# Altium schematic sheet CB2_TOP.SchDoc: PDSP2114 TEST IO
size A2; Engineer: SHOWELL; DocumentNumber: 1; Revision: 1.00; SheetNumber: 1; SheetTotal: 1; PageSetup: Record=PageOptions|CenterHorizontal=True|CenterVertical=True|PrintScale=1.47|XCorrection=1.00|YCorrection=1.00|PrintKind=0|BorderSize=5000000|LeftOffset=0|BottomOffset=0|Orientation=2|PaperLength=1000|PaperWidth=1000|Scale=100|PaperSource=7|PrintQuality=-4|MediaType=1|DitherType=10|PaperKind=A2|PrintScaleMode=1
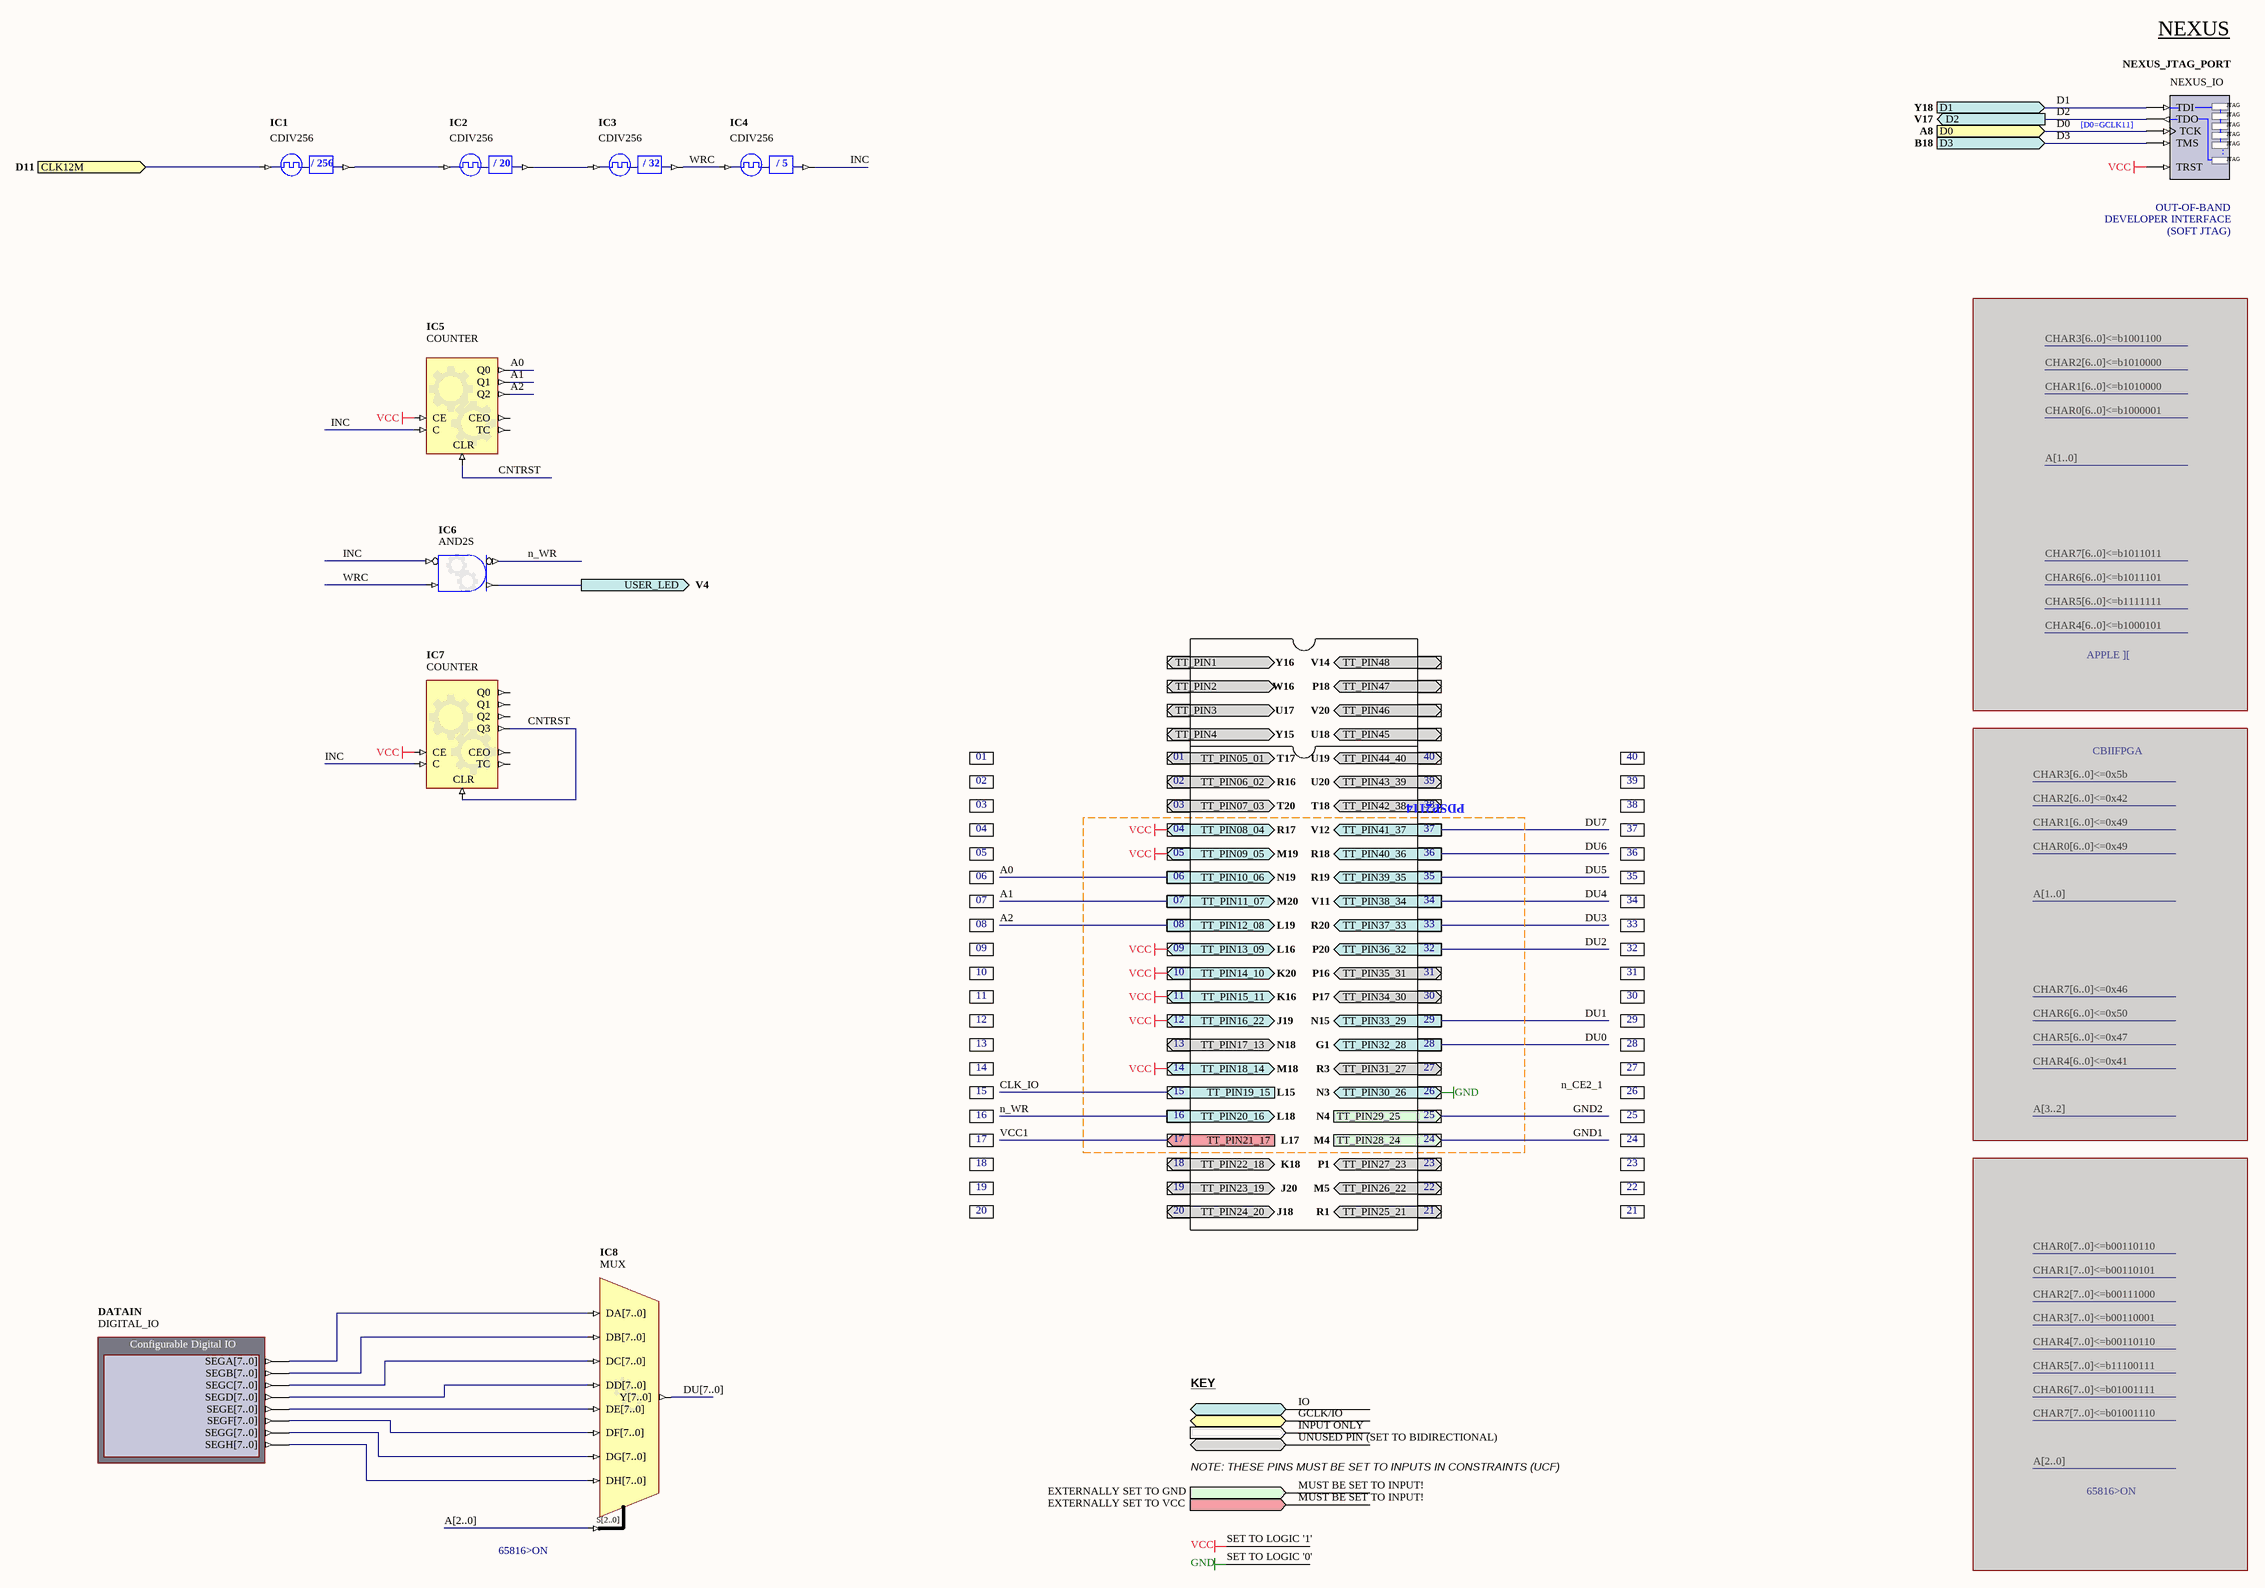
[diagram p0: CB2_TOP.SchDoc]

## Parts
DATAIN  DIGITAL_IO
IC1  CDIV256
IC2  CDIV256
IC3  CDIV256
IC4  CDIV256
IC5  COUNTER
IC6  AND2S
IC7  COUNTER
IC8  MUX
NEXUS_JTAG_PORT  NEXUS_IO

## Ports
CLK12M (in, see D11), D0 (in, see A8), D1 (in, see Y18), D2 (out, see V17), D3 (in, see B18), TT_PIN1 (bidir, see Y16), TT_PIN2 (bidir, see W16), TT_PIN3 (bidir, see U17), TT_PIN4 (bidir, see Y15), TT_PIN05_01 (bidir, see T17), TT_PIN06_02 (bidir, see R16), TT_PIN07_03 (bidir, see T20), TT_PIN08_04 (out, see R17), TT_PIN09_05 (out, see M19), TT_PIN10_06 (out, see N19), TT_PIN11_07 (out, see M20), TT_PIN12_08 (out, see L19), TT_PIN13_09 (out, see L16), TT_PIN14_10 (out, see K20), TT_PIN15_11 (out, see K16), TT_PIN16_22 (out, see J19), TT_PIN17_13 (bidir, see N18), TT_PIN18_14 (out, see M18), TT_PIN19_15 (in, see L15), TT_PIN20_16 (out, see L18), TT_PIN21_17 (in, see L17), TT_PIN22_18 (bidir, see K18), TT_PIN23_19 (bidir, see J20), TT_PIN24_20 (bidir, see J18), TT_PIN25_21 (bidir, see R1), TT_PIN26_22 (bidir, see M5), TT_PIN27_23 (bidir, see P1), TT_PIN28_24 (in, see M4), TT_PIN29_25 (in, see N4), TT_PIN30_26 (out, see N3), TT_PIN31_27 (bidir, see R3), TT_PIN32_28 (out, see G1), TT_PIN33_29 (out, see N15), TT_PIN34_30 (bidir, see P17), TT_PIN35_31 (bidir, see P16), TT_PIN36_32 (out, see P20), TT_PIN37_33 (out, see R20), TT_PIN38_34 (out, see V11), TT_PIN39_35 (out, see R19), TT_PIN40_36 (out, see R18), TT_PIN41_37 (out, see V12), TT_PIN42_38 (bidir, see T18), TT_PIN43_39 (bidir, see U20), TT_PIN44_40 (bidir, see U19), TT_PIN45 (bidir, see U18), TT_PIN46 (bidir, see V20), TT_PIN47 (bidir, see P18), TT_PIN48 (bidir, see V14), USER_LED (out, see V4)

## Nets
VCC: IC5.CE IC7.CE NEXUS_JTAG_PORT.TRST ; port TT_PIN09_05, port TT_PIN13_09, port TT_PIN16_22, port TT_PIN15_11, port TT_PIN14_10, port TT_PIN18_14, port TT_PIN08_04
A0: IC5.Q0 ; port TT_PIN10_06
A1: IC5.Q1 ; port TT_PIN11_07
A2: IC5.Q2 ; port TT_PIN12_08
CLK12M: IC1.CLKIN ; port CLK12M
CNTRST: IC5.CLR IC7.CLR IC7.Q3
D0: NEXUS_JTAG_PORT.TCK ; port D0
D1: NEXUS_JTAG_PORT.TDI ; port D1
D2: NEXUS_JTAG_PORT.TDO ; port D2
D3: NEXUS_JTAG_PORT.TMS ; port D3
INC: IC4.CLKDV IC5.C IC6.I0 IC7.C
n_WR: IC6.NO ; port TT_PIN20_16
USER_LED: IC6.O ; port USER_LED
WRC: IC3.CLKDV IC4.CLKIN IC6.I1
NetIC1_CLKDV: IC1.CLKDV IC2.CLKIN
NetIC2_CLKDV: IC2.CLKDV IC3.CLKIN

Not connected (* = marked no-connect by the designer): DATAIN SEGA[7..0] SEGB[7..0] SEGC[7..0] SEGD[7..0] SEGE[7..0] SEGF[7..0] SEGG[7..0] SEGH[7..0]; IC5 CEO TC; IC7 CEO Q0 Q1 Q2 TC; IC8 DA[7..0] DB[7..0] DC[7..0] DD[7..0] DE[7..0] DF[7..0] DG[7..0] DH[7..0] S[2..0] Y[7..0]

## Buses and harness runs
bus A[2..0]
bus DU[7..0]

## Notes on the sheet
- NEXUS
- (near NEXUS_JTAG_PORT) [D0=GCLK11]
- DEVELOPER INTERFACE
- (near NEXUS_JTAG_PORT) OUT-OF-BAND
- (SOFT JTAG)
- APPLE ][
- 01
- 02
- 40
- 39
- CBIIFPGA
- 03
- 04
- 38
- 37
- PDSP2114
- 05
- 06
- 07
- 36
- 35
- 34
- 08
- 09
- 33
- 32
- 10
- 11
- 12
- 31
- 30
- 29
- 13
- 14
- 28
- 27
- 15
- 16
- 17
- 26
- 25
- 24
- 18
- 19
- 23
- 22
- 20
- 21
- KEY
- IO
- GCLK/IO
- INPUT ONLY
- UNUSED PIN (SET TO BIDIRECTIONAL)
- EXTERNALLY SET TO GND
- NOTE: THESE PINS MUST BE SET TO INPUTS IN CONSTRAINTS (UCF)
- MUST BE SET TO INPUT!
- 65816>ON
- EXTERNALLY SET TO VCC
- VCC
- GND
- SET TO LOGIC '1'
- SET TO LOGIC '0'
- Labels drawn without touching a wire or pin: n_CE2_1

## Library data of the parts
DATAIN = DIGITAL_IO: Configurable Digital IO; NEXUS_CORE: Instrument; NEXUS_JTAG_DEVICE: True; NEXUS_JTAG_ORDER: 0; ConfigurationParameters: {}Version[2.0]{}StorageType[3]{}InterfaceType[Parallel]{}SchCompWidth[140]{}NoInputs[ ]{}Output0Name[SEGA{1}7..0{2}]{}Output0Width[8]{}Output0InitValue[67]{}Output0Kind[Numeric]{}Output0NumRadix[Binary]{}Output1Name[SEGB{1}7..0{2}]{}Output1Width[8]{}Output1InitValue[66]{}Output1Kind[Numeric]{}Output1NumRadix[Binary]{}Output2Name[SEGC{1}7..0{2}]{}Output2Width[8]{}Output2InitValue[73]{}Output2Kind[Numeric]{}Output2NumRadix[Binary]{}Output3Name[SEGD{1}7..0{2}]{}Output3Width[8]{}Output3InitValue[73]{}Output3Kind[Numeric]{}Output3NumRadix[Binary]{}Output4Name[SEGE{1}7..0{2}]{}Output4Width[8]{}Output4InitValue[70]{}Output4Kind[Numeric]{}Output4NumRadix[Binary]{}Output5Name[SEGF{1}7..0{2}]{}Output5Width[8]{}Output5InitValue[80]{}Output5Kind[Numeric]{}Output5NumRadix[Binary]{}Output6Name[SEGG{1}7..0{2}]{}Output6Width[8]{}Output6InitValue[71]{}Output6Kind[Numeric]{}Output6NumRadix[Binary]{}Output7Name[SEGH{1}7..0{2}]{}Output7Width[8]{}Output7InitValue[65]{}Output7Kind[Numeric]{}Output7NumRadix[Binary]{}Designator[DATAIN]{}InternalID[0]{}
IC1 = CDIV256DC50: Clock Divider by 256 with 50% Duty Cycle Output; DivisorRate: 256; ArchiveName: GENERIC; VHDLIB_SIM: GENERIC_LIB; DutyCycle: 50
IC2 = CDIV20DC50: Clock Divider by 20 with 50% Duty Cycle Output; DivisorRate: 20; ArchiveName: GENERIC; VHDLIB_SIM: GENERIC_LIB; DutyCycle: 50
IC3 = CDIV32DC50: Clock Divider by 32 with 50% Duty Cycle Output; DivisorRate: 32; ArchiveName: GENERIC; VHDLIB_SIM: GENERIC_LIB; DutyCycle: 50
IC4 = CDIV5: Clock Divider by 5; DivisorRate: 5; ArchiveName: GENERIC; VHDLIB_SIM: GENERIC_LIB
IC5 = COUNTER: Configurable Counter; ConfiguratorName: GENERIC_COUNTER; ConfigurationParameters: {}Version[1.0]{}Type[Binary]{}SyncReset[False]{}NegativeClockEdge[False]{}FixedDirection[True]{}IsIncrement[True]{}SignalWidth[3]{}MaxValue[7]{}BusOutput[False]{}Loadable[False]{}BusInput[False]{}ShowPinNames[True]{}
IC6 = GATE: Configurable Generic Gate; ConfiguratorName: GENERIC_GATE; ConfigurationParameters: {}Version[1.1]{}GateKind[AND]{}BusInput[False]{}GateInputType[Bit]{}GateOutputOption[Normal/Inverted]{}BusWidth[8]{}RegisterOutputs[False]{}NegativeClockEdge[False]{}InputCount[2]{}InputInvert0[True]{}InputInvert1[False]{}
IC7 = COUNTER: Configurable Counter; ConfiguratorName: GENERIC_COUNTER; ConfigurationParameters: {}Version[1.0]{}Type[Binary]{}SyncReset[False]{}NegativeClockEdge[False]{}FixedDirection[True]{}IsIncrement[True]{}SignalWidth[4]{}MaxValue[15]{}BusOutput[False]{}Loadable[False]{}BusInput[False]{}ShowPinNames[True]{}
IC8 = MUX: Configurable Mutliplexer; ConfiguratorName: GENERIC_MULTIPLEXER; ConfigurationParameters: {}Version[1.0]{}ShowEnable[False]{}BusInputs[True]{}BusOutputs[True]{}SignalWidth[8]{}Type[Multiplexer]{}RegisterOutputs[False]{}NegativeClockEdge[True]{}ShowPinNames[True]{}InvertSingleSignal[False]{}SignalCount[8]{}Invert0[False]{}Invert1[False]{}Invert2[False]{}Invert3[False]{}Invert4[False]{}Invert5[False]{}Invert6[False]{}Invert7[False]{}
NEXUS_JTAG_PORT = NEXUS_JTAG_PORT: Soft Nexus-Chain Connector; NEXUS_JTAG_CONNECTOR: True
